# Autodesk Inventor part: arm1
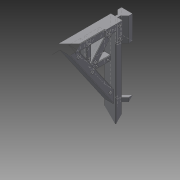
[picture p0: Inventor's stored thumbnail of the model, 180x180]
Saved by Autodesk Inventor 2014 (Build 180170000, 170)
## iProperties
Created: 2013-07
Part Number: arm1
Material: Generic
Document SubType Name: Modeling
Designer: Brent J. Rosenburgh
Density: 1 g/cm^3
Appearance: Default
d0: 8.000 mm
d1: 119.000 mm
d2: 0.00 deg
d3: 19.000 mm
d4: 0.00 deg
d5: 14.000 mm
d6: 0.00 deg
d7: 12.000 mm
d8: 0.00 deg
d9: 10.000 mm
d10: 0.00 deg
d11: 8.000 mm
d12: 0.00 deg
d13: 1.000 mm
d14: 0.00 deg
d15: 1.000 mm
d16: 0.00 deg
d17: 1.000 mm
d18: 0.00 deg
d19: 1.000 mm
d20: 0.00 deg
d21: 1.000 mm
d22: 0.00 deg
d23: 1.000 mm
d24: 0.00 deg
d25: 8.000 mm
d26: 0.00 deg
d27: 8.000 mm
d30: 5.000 mm
d33: 4.000 mm
d34: 0.00 deg
d35: 6.000 mm
d36: 4.000 mm
d37: 0.00 deg
d38: 3.000 mm
d41: 1.000 mm
d44: 0.600 mm
d47: 0.600 mm
d50: 1.850 mm
Author: Brent J. Rosenburgh
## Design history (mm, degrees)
sketch "Sketch1"
  geometry: L1 (-7, 5)-(7, 5); L2 (7, 5)-(7, 0); L3 (7, 0)-(2, -5); L4 (-7, 5)-(-7, 0); L5 (-7, 0)-(-2, -5); L6 (-2, -5)-(-1.627, -5.373); L7 (-1.627, -5.373)-(-1.627, -8.541); L8 (2, -5)-(1.627, -5.373); L9 (1.627, -5.373)-(1.627, -8.541); L10 (1.627, -8.541)-(7, -8.541); L11 (-1.627, -8.541)-(-7, -8.541); L12 (-7, -8.541)-(-7, -16.541); L13 (-7, -16.541)-(7, -16.541); L14 (7, -16.541)-(7, -8.541); 1 further point
  constraints: 28 end point, 5 parallel, 5 perpendicular, 2 collinear, 1 horizontal
  dimensions: "d0" = 8 distance of L11.end L12.end
extrude "Extrusion1" new body sketch "Sketch1" distance "d1" = 119; taper "d2" = 0 deg
sketch "Sketch2"
  geometry: L1 (0, 8)-(-119, 8) reference; L2 (-30, 8)-(-89, 8); L3 (-89, 8)-(-89, 24); L4 (-89, 24)-(-30, 24); L5 (-30, 24)-(-30, 8); 1 further point
  constraints: 8 end point, 2 parallel, 1 horizontal, 1 perpendicular, 1 point on line
extrude "Extrusion2" cut sketch "Sketch2" distance "d3" = 19; taper "d4" = 0 deg
sketch "Sketch3"
  geometry: L1 (0, 0)-(119, 0) reference; L2 (0, 8)-(119, 8) reference; L3 (119, 0)-(119, -80); L4 (119, -80)-(111, -80); L5 (111, -80)-(111, 0); 1 further point
  constraints: 6 end point, 2 perpendicular, 1 parallel, 1 point on line
extrude "Extrusion3" join sketch "Sketch3" distance "d5" = 14; taper "d6" = 0 deg
sketch "Sketch4"
  geometry: L1 (0, 0)-(111, 0) reference; L2 (111, 0)-(111, -80) reference; L3 (111, -56)-(30, 0); L4 (46, 0)-(111, -44.938); 1 further point
  constraints: 4 end point, 4 point on line, 1 parallel
extrude "Extrusion4" join sketch "Sketch4" distance "d7" = 12; taper "d8" = 0 deg
sketch "Sketch5"
  geometry: L1 (46, 0)-(111, 0) reference; L2 (111, 0)-(111, -44.938) reference; L3 (111, -44.938)-(46, 0) reference; L4 (105, 0)-(78.5, -22.469); L5 (111, -6)-(85.703, -27.449); 1 further point
  constraints: 4 end point, 3 point on line, 1 midpoint, 1 parallel
extrude "Extrusion5" join sketch "Sketch5" distance "d9" = 10; taper "d10" = 0 deg
sketch "Sketch6"
  geometry: L1 (81.627, 3)-(75.061, 3); L2 (75.061, 3)-(75.061, -25.469); L3 (75.061, -25.469)-(81.627, -25.469); L4 (81.627, -25.469)-(81.627, 3); L5 (113, -24.592)-(81.627, -24.592); L6 (81.627, -24.592)-(81.627, -30.232); L7 (81.627, -30.232)-(113, -30.232); L8 (113, -30.232)-(113, -24.592); 1 further point
  constraints: 16 end point, 4 parallel, 2 horizontal, 2 perpendicular
extrude "Extrusion6" join sketch "Sketch6" distance "d11" = 8; taper "d12" = 0 deg
sketch "Sketch7"
  geometry: L1 (0, 8)-(-119, 8) reference; L2 (-119, 8)-(-119, -80) reference; L3 (-111, -80)-(-111, 0) reference; L4 (0, 0)-(-111, 0) reference; L5 (-97, 0)-(-97, 8); L6 (-111, -14)-(-119, -14); 1 further point
  constraints: 4 end point, 4 point on line, 2 perpendicular
extrude "Extrusion7" join sketch "Sketch7" distance "d13" = 1; taper "d14" = 0 deg
sketch "Sketch8"
  geometry: L1 (-103.938, -47.474)-(-105.67, -46.474); L2 (-105.67, -46.474)-(-105.67, -44.474); L3 (-105.67, -44.474)-(-103.938, -43.474); L4 (-103.938, -43.474)-(-102.206, -44.474); L5 (-102.206, -44.474)-(-102.206, -46.474); L6 (-102.206, -46.474)-(-103.938, -47.474); L7 (-45, -7)-(-46.732, -6); L8 (-46.732, -6)-(-46.732, -4); L9 (-46.732, -4)-(-45, -3); L10 (-45, -3)-(-43.268, -4); L11 (-43.268, -4)-(-43.268, -6); L12 (-43.268, -6)-(-45, -7); L13 (-78.5, -25.888)-(-76.768, -26.888); L14 (-80.232, -26.888)-(-78.5, -25.888); L15 (-76.768, -28.888)-(-78.5, -29.888); L16 (-80.232, -28.888)-(-80.232, -26.888); L17 (-78.5, -29.888)-(-80.232, -28.888); L18 (-76.768, -26.888)-(-76.768, -28.888); 4 further points
  constraints: 36 end point, 39 other
extrude "Extrusion8" join sketch "Sketch8" distance "d15" = 1; taper "d16" = 0 deg
sketch "Sketch9"
  geometry: L1 (-101, 2)-(-102.732, 3); L2 (-102.732, 3)-(-102.732, 5); L3 (-102.732, 5)-(-101, 6); L4 (-101, 6)-(-99.268, 5); L5 (-99.268, 5)-(-99.268, 3); L6 (-99.268, 3)-(-101, 2); L7 (-115, -12)-(-116.732, -11); L8 (-116.732, -11)-(-116.732, -9); L9 (-116.732, -9)-(-115, -8); L10 (-115, -8)-(-113.268, -9); L11 (-113.268, -9)-(-113.268, -11); L12 (-113.268, -11)-(-115, -12); L13 (-115, 2)-(-116.732, 3); L14 (-116.732, 3)-(-116.732, 5); L15 (-116.732, 5)-(-115, 6); L16 (-115, 6)-(-113.268, 5); L17 (-113.268, 5)-(-113.268, 3); L18 (-113.268, 3)-(-115, 2); 4 further points
  constraints: 36 end point, 39 other
extrude "Extrusion9" join sketch "Sketch9" distance "d17" = 1; taper "d18" = 0 deg
sketch "Sketch10"
  geometry: L1 (-106, -7)-(-107.732, -6); L2 (-107.732, -6)-(-107.732, -4); L3 (-107.732, -4)-(-106, -3); L4 (-106, -3)-(-104.268, -4); L5 (-104.268, -4)-(-104.268, -6); L6 (-104.268, -6)-(-106, -7); L7 (-85.703, -24)-(-87.435, -23); L8 (-87.435, -23)-(-87.435, -21); L9 (-87.435, -21)-(-85.703, -20); L10 (-85.703, -20)-(-83.971, -21); L11 (-83.971, -21)-(-83.971, -23); L12 (-83.971, -23)-(-85.703, -24); 3 further points
  constraints: 24 end point, 26 other
extrude "Extrusion10" join sketch "Sketch10" distance "d19" = 1; taper "d20" = 0 deg
sketch "Sketch11"
  geometry: L1 (-79.811, -18)-(-79.155, -16.865); L2 (-79.155, -16.865)-(-77.845, -16.865); L3 (-77.845, -16.865)-(-77.189, -18); L4 (-77.189, -18)-(-77.845, -19.135); L5 (-77.845, -19.135)-(-79.155, -19.135); L6 (-79.155, -19.135)-(-79.811, -18); L7 (-79.811, -4)-(-79.155, -2.865); L8 (-79.155, -2.865)-(-77.845, -2.865); L9 (-77.845, -2.865)-(-77.189, -4); L10 (-77.189, -4)-(-77.845, -5.135); L11 (-77.845, -5.135)-(-79.155, -5.135); L12 (-79.155, -5.135)-(-79.811, -4); 3 further points
  constraints: 24 end point, 26 other
extrude "Extrusion11" join sketch "Sketch11" distance "d21" = 1; taper "d22" = 0 deg
sketch "Sketch12"
  geometry: L1 (-107, -28.841)-(-108.237, -28.126); L2 (-108.237, -28.126)-(-108.237, -26.698); L3 (-108.237, -26.698)-(-107, -25.983); L4 (-107, -25.983)-(-105.763, -26.698); L5 (-105.763, -26.698)-(-105.763, -28.126); L6 (-105.763, -28.126)-(-107, -28.841); L7 (-92, -28.841)-(-93.237, -28.126); L8 (-93.237, -28.126)-(-93.237, -26.698); L9 (-93.237, -26.698)-(-92, -25.983); L10 (-92, -25.983)-(-90.763, -26.698); L11 (-90.763, -26.698)-(-90.763, -28.126); L12 (-90.763, -28.126)-(-92, -28.841); 3 further points
  constraints: 24 end point, 26 other
extrude "Extrusion12" join sketch "Sketch12" distance "d23" = 1; taper "d24" = 0 deg
sketch "Sketch13"
  geometry: L1 (14, 0)-(-8, 0); L2 (-8, 0)-(-8, 22); L3 (-8, 22)-(14, 22); L4 (14, 22)-(14, 0); 1 further point
  constraints: 8 end point, 2 parallel, 1 horizontal, 1 perpendicular
extrude "Extrusion13" join sketch "Sketch13" distance "d25" = 8; taper "d26" = 0 deg
chamfer "Chamfer1" distance "d27" = 8; stored, may be unused: second distance "d28" = 2, angle "d29" = 45 deg
chamfer "Chamfer2" distance "d30" = 5; stored, may be unused: second distance "d31" = 2, angle "d32" = 45 deg
sketch "Sketch14"
  geometry: L1 (8.5, -9.364)-(8.449, -15.556); L2 (8.449, -15.556)-(4.034, -19.898); L3 (4.034, -19.898)-(-2.158, -19.847); L4 (-2.158, -19.847)-(-6.5, -15.432); L5 (-6.5, -15.432)-(-6.449, -9.24); L6 (-6.449, -9.24)-(-2.034, -4.898); L7 (-2.034, -4.898)-(4.158, -4.949); L8 (4.158, -4.949)-(8.5, -9.364); 2 further points
  constraints: 16 end point, 17 other
extrude "Extrusion14" cut sketch "Sketch14" distance "d33" = 4; taper "d34" = 0 deg
sketch "Sketch15"
  geometry: C1 r 3 at (0.938, -12.335); 1 further point
  constraints: 1 centre point
  dimensions: "d35" = 6 diameter of C1
extrude "Extrusion15" cut sketch "Sketch15" distance "d36" = 4; taper "d37" = 0 deg
chamfer "Chamfer3" distance "d38" = 3; stored, may be unused: second distance "d39" = 2, angle "d40" = 45 deg
chamfer "Chamfer4" distance "d41" = 1; stored, may be unused: second distance "d42" = 2, angle "d43" = 45 deg
chamfer "Chamfer5" distance "d44" = 0.6; stored, may be unused: second distance "d45" = 2, angle "d46" = 45 deg
chamfer "Chamfer6" distance "d47" = 0.6; stored, may be unused: second distance "d48" = 2, angle "d49" = 45 deg
chamfer "Chamfer7" distance "d50" = 1.85; stored, may be unused: second distance "d51" = 2, angle "d52" = 45 deg
body "Solid1"
